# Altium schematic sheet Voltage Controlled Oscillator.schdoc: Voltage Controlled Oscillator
size A4; Organization: Altium Limited; Address1: L3, 12a Rodborough Rd; Address2: Frenchs Forest; Address3: NSW; Address4: Australia 2086; DocumentNumber: 1; SheetNumber: 1; SheetTotal: 1
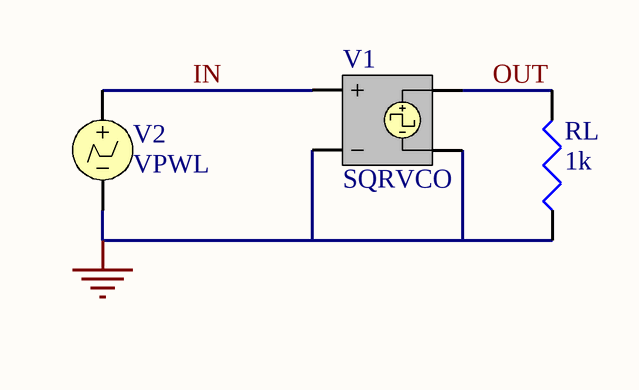
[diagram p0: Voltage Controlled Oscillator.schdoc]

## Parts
RL  1k
V1  SQRVCO
V2  VPWL

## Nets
GND: RL.2(BOT) V1.2(NC-) V1.4(N-) V2.2
IN: V1.1(NC+) V2.1
OUT: RL.1(TOP) V1.3(N+)

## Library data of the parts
RL = RES: Resistor
V1 = SQRVCO: Square Voltage Controlled Oscillator
V2 = VPWL: Piecewise Linear Voltage Source; Time-Value Pairs: 0 .1 2m .3 4m 1 6m 1.5 8m .5 10m 2.5 12m 4 14m .1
